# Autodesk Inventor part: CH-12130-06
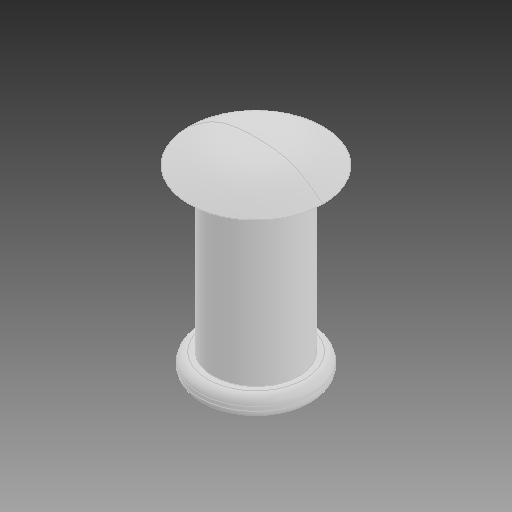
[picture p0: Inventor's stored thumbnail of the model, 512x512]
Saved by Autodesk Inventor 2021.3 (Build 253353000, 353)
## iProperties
Created: 2020-03
Part Number: CH-12130-06
Material: Ogólny
Document SubType Name: Modeling
Designer: Przemyslaw Krecisz
Density: 1 g/cm^3
Appearance: Domyślna
Author: Przemyslaw Krecisz
Revision Number: ÈÎºÎ
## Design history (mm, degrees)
feature "Ô²½Ç3"
node "Bryła1"
